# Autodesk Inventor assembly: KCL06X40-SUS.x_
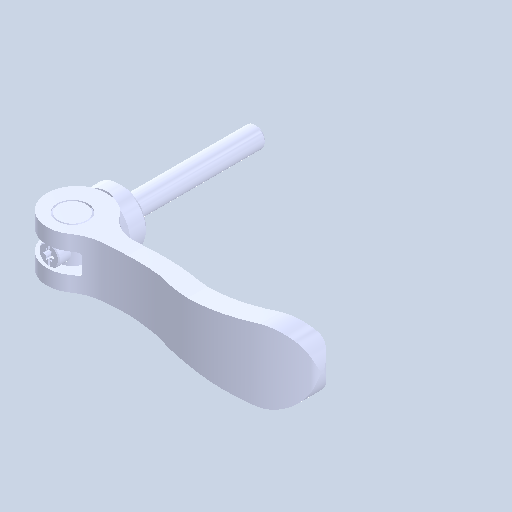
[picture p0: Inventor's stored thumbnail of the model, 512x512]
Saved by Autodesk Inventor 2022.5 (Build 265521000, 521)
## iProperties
Created: 2024-08
Part Number: KCL06X40-SUS.x_
Document SubType Name: Assembly
Designer: ImaoCorp
Author: ImaoCorp
Sending System: SOLIDWORKS 2022-2022290
MC: AMD64
MC_MODEL: Intel64 Family 6 Model 60 Stepping 3, GenuineIntel
OS: Windows_NT
FRU: Parasolid Version 33.1, build 260,  4-25-2022
FORMAT: text
GUISE: transmit
KEY: FILEKCL06X40-SUS.x_t
DATE: Thu Aug 29 10:49:58 2024
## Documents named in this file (5)
- Y:\5.更新分\2024年対応\1001_KCL\データ\kcl06x40-sus\KCL06X40-SUS.x_.iam
- Y:\5.更新分\2024年対応\1001_KCL\データ\kcl06x40-sus\KCL06X40-SUS_01.ipt
- Y:\5.更新分\2024年対応\1001_KCL\データ\kcl06x40-sus\KCL06X40-SUS_02.ipt
- Y:\5.更新分\2024年対応\1001_KCL\データ\kcl06x40-sus\KCL06X40-SUS_03.ipt
- Y:\5.更新分\2024年対応\1001_KCL\データ\kcl06x40-sus\KCL06X40-SUS_04.ipt
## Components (4 placed, 4 different names)
1. KCL06X40-SUS_01
2. KCL06X40-SUS_02
3. KCL06X40-SUS_03
4. KCL06X40-SUS_04
